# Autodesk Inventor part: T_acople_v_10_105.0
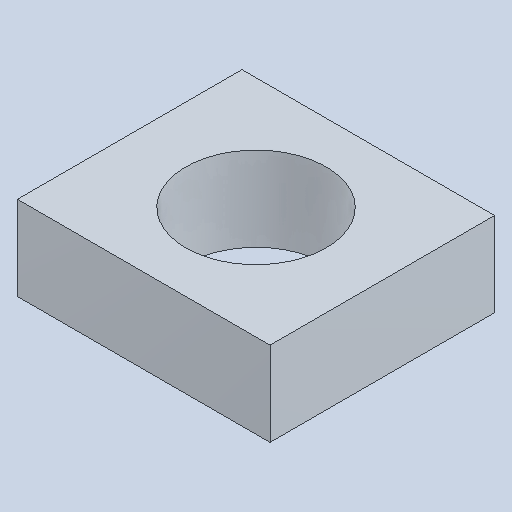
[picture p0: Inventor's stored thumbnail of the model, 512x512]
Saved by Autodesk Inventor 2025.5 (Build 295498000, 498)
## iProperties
Created: 2026-10
Part Number: T_acople_v_10_105.0
Material: Genérico
Document SubType Name: Modeling
Designer: Luis M
Density: 1 g/cm^3
Appearance: Valor por defecto
Author: Luis M
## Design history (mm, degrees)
feature "Base1"
node "Sólido1"
